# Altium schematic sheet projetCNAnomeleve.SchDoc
size A4
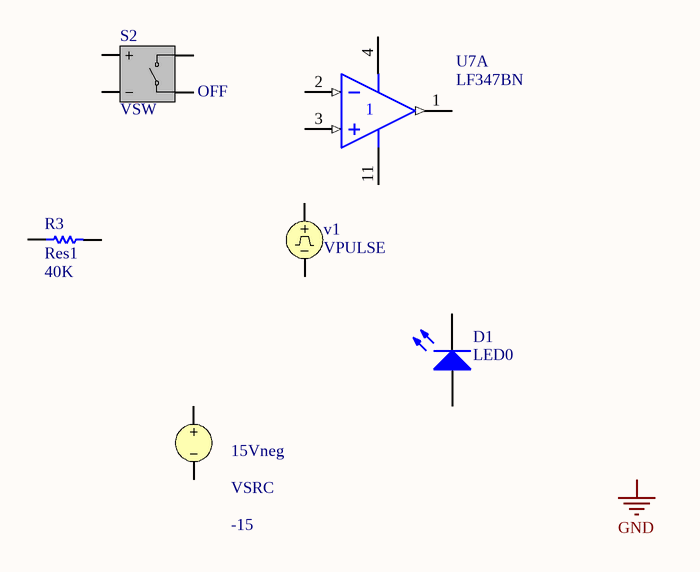
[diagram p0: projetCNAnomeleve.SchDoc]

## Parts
15Vneg  VSRC  value -15
D1  LED0  [LED-0]
R3  Res1  value 40K  [AXIAL-0.3]
S2  VSW  Initial Condition: OFF
U7  LF347BN  [646-06]  (part A of 4)
v1  VPULSE

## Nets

Not connected (* = marked no-connect by the designer): 15Vneg 1 2; D1 1(A) 2(K); R3 1 2; S2 1(N1+) 2(N1-) 3(N2+) 4(N2-); U7 1(OUT) 2(IN-) 3(IN+) 4(V+) 11(V-); v1 1 2

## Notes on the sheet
- Labels drawn without touching a wire or pin: GND

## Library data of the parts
15Vneg = VSRC: Voltage Source; Note: PCB Footprint - Not required
D1 = LED0: Typical INFRARED GaAs LED
R3 = Res1: Resistor
S2 = VSW: Voltage Controlled Switch
U7 = LF347BN: Quad JFET Input Operational Amplifier, Internally Compensated
v1 = VPULSE: Pulse Voltage Source; Note: PCB Footprint - Not required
